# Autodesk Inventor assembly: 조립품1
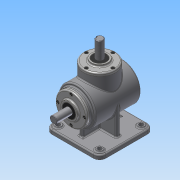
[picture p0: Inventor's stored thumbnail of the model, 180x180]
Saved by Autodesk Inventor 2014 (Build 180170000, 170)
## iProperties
Created: 2015-07
Part Number: 조립품1
Document SubType Name: Assembly
Designer: net
Author: net
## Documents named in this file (14)
- C:\Users\net\Desktop\450705V1028\조립품1.iam
- C:\Users\net\Desktop\450705V1028\본체.ipt
- C:\Users\net\Desktop\450705V1028\커버.ipt
- C:\Users\net\Desktop\450705V1028\베어링 6203.ipt
- C:\Users\net\Desktop\450705V1028\서브 축.ipt
- 서브 축.ipt
- C:\Users\net\Desktop\450705V1028\키 4x4.ipt
- C:\Users\net\Desktop\450705V1028\서브 베벨기어.ipt
- C:\Users\net\Desktop\450705V1028\메인 축.ipt
- 메인 축.ipt
- C:\Users\net\Desktop\450705V1028\키 5x5.ipt
- C:\Users\net\Desktop\450705V1028\메인 베벨기어.ipt
- C:\Users\net\Desktop\450705V1028\오일실.ipt
- C:\Users\net\Desktop\450705V1028\M4.ipt
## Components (8 placed, 1 different names)
1. M4:1
2. M4:3
3. M4:4
4. M4:5
5. M4:2
6. M4:6
7. M4:7
8. M4:8
